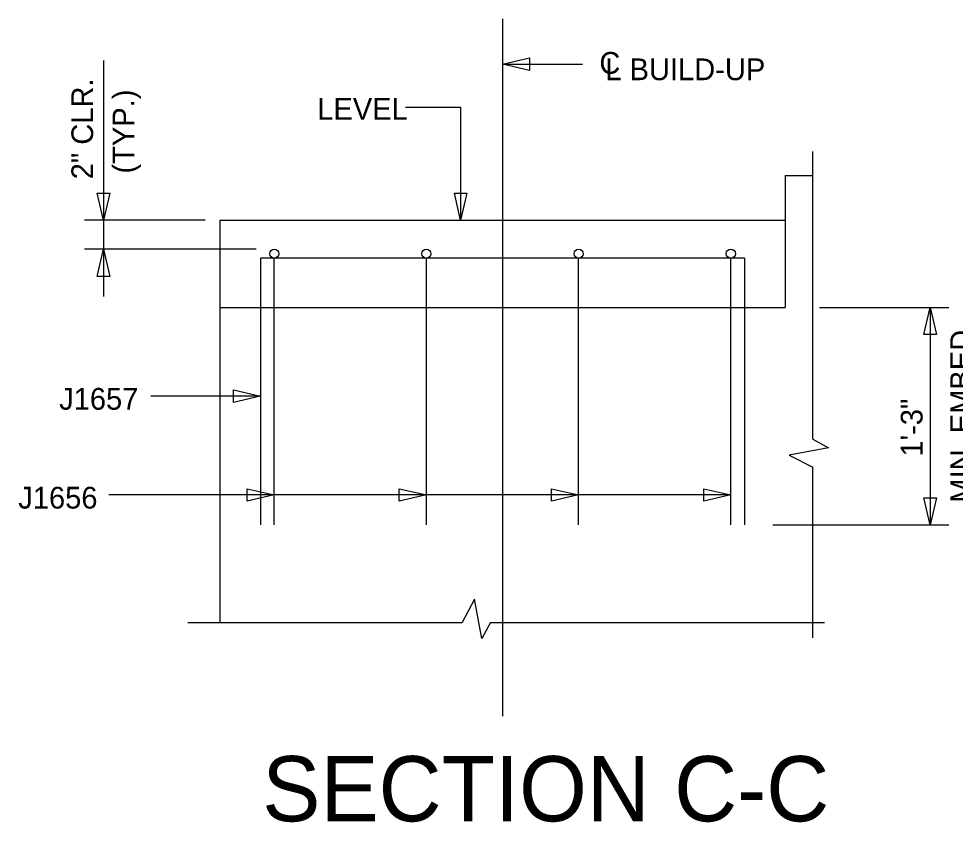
# Model space of a CAD drawing. Extents: x -133.1 to -97, y -1.7 to 20.3.
# Drawn here: x -108.44 to -103.06, y 4.57 to 9.19 of the extents above; entities that cross this region are included whole.
import ezdxf

# ---------------------------------------------------------------- set-up
doc = ezdxf.new("R2010")
doc.units = 0
for name, color, linetype in [('BR_AUTO DIMENSION', 7, 'Continuous'), ('BR_CENTER LINES', 7, 'Continuous'), ('BR_CONCRETE', 7, 'Continuous'), ('BR_REBAR', 7, 'Continuous'), ('BR_TEXT', 7, 'Continuous'), ('Default', 7, 'Continuous')]:
    doc.layers.add(name, color=color, linetype=linetype)

msp = doc.modelspace()

# ---------------------------------------------------------------- linework, layer by layer
at = {"layer": 'BR_AUTO DIMENSION'}
for p, q in [((-107.9547, 8.9515), (-107.9547, 7.5961)), ((-105.6611, 8.9313), (-105.2017, 8.9313)), ((-106.2188, 8.6848), (-105.902, 8.6848)), ((-105.902, 8.6848), (-105.902, 8.0346)), ((-107.3697, 8.0346), (-108.0639, 8.0346)), ((-107.0766, 7.8679), (-108.0639, 7.8679)), ((-103.8393, 7.5336), (-103.0962, 7.5336)), ((-103.2023, 7.5336), (-103.2023, 6.2836)), ((-107.0517, 7.0236), (-107.6836, 7.0236)), ((-104.3486, 6.4554), (-107.9245, 6.4554)), ((-107.7444, 6.4554), (-107.8245, 6.4554)), ((-106.9736, 6.4554), (-107.0537, 6.4554)), ((-106.0986, 6.4554), (-106.1787, 6.4554)), ((-105.2236, 6.4554), (-105.3037, 6.4554)), ((-104.3486, 6.4554), (-104.4287, 6.4554)), ((-104.1075, 6.2836), (-103.0962, 6.2836))]:
    msp.add_line(p, q, dxfattribs=at)
for points in [[(-105.5051, 8.8953), (-105.6611, 8.9313), (-105.5051, 8.9673)], [(-107.9187, 8.1906), (-107.9547, 8.0346), (-107.9907, 8.1906)], [(-105.866, 8.1906), (-105.902, 8.0346), (-105.938, 8.1906)], [(-107.9907, 7.7119), (-107.9547, 7.8679), (-107.9187, 7.7119)], [(-103.2383, 7.3776), (-103.2023, 7.5336), (-103.1663, 7.3776)], [(-107.2077, 7.0596), (-107.0517, 7.0236), (-107.2077, 6.9876)], [(-107.1296, 6.4914), (-106.9736, 6.4554), (-107.1296, 6.4194)], [(-106.2546, 6.4914), (-106.0986, 6.4554), (-106.2546, 6.4194)], [(-105.3796, 6.4914), (-105.2236, 6.4554), (-105.3796, 6.4194)], [(-104.5046, 6.4914), (-104.3486, 6.4554), (-104.5046, 6.4194)], [(-103.1663, 6.4396), (-103.2023, 6.2836), (-103.2383, 6.4396)]]:
    msp.add_lwpolyline(points, close=True, dxfattribs=at)
at = {"layer": 'BR_CENTER LINES'}
msp.add_line((-105.6611, 9.1925), (-105.6611, 5.1843), dxfattribs=at)
at = {"layer": 'BR_CONCRETE'}
for p, q in [((-104.0361, 8.2914), (-104.0361, 7.5336)), ((-104.0361, 8.2914), (-103.878, 8.2914)), ((-107.2861, 8.0346), (-107.2861, 7.5336)), ((-107.2861, 8.0346), (-104.0361, 8.0346)), ((-107.2861, 7.5336), (-104.0361, 7.5336)), ((-107.2861, 7.5336), (-107.2861, 5.7216))]:
    msp.add_line(p, q, dxfattribs=at)
at = {"layer": 'BR_REBAR'}
for p, q in [((-104.2704, 7.8159), (-107.0517, 7.8159)), ((-107.0517, 7.8159), (-107.0517, 6.2836)), ((-106.9736, 6.2836), (-106.9736, 7.8159)), ((-106.0986, 6.2836), (-106.0986, 7.8159)), ((-105.2236, 6.2836), (-105.2236, 7.8159)), ((-104.3486, 6.2836), (-104.3486, 7.8159)), ((-104.2704, 7.8159), (-104.2704, 6.2836))]:
    msp.add_line(p, q, dxfattribs=at)
for centre in [(-106.9736, 7.8419), (-106.0986, 7.8419), (-105.2236, 7.8419), (-104.3486, 7.8419)]:
    msp.add_circle(centre, 0.0261, dxfattribs=at)
at = {"layer": 'Default'}
for p, q in [((-103.878, 6.7758), (-103.878, 8.43)), ((-103.878, 5.6342), (-103.878, 6.6142)), ((-107.47, 5.7216), (-105.8926, 5.7216)), ((-105.731, 5.7216), (-103.8107, 5.7216))]:
    msp.add_line(p, q, dxfattribs=at)
for points in [[(-103.878, 6.7758), (-103.7866, 6.7262), (-104.0128, 6.6837), (-103.878, 6.6142)], [(-105.731, 5.7216), (-105.7806, 5.6302), (-105.8231, 5.8564), (-105.8926, 5.7216)]]:
    msp.add_lwpolyline(points, dxfattribs=at)

# ---------------------------------------------------------------- texts
at = {"layer": 'BR_AUTO DIMENSION'}
for s, p in [('C', (-105.1045, 8.8763)), ('L BUILD-UP', (-105.0702, 8.8393))]:
    msp.add_text(s, height=0.125, dxfattribs=at).set_placement(p)
for s, height, rotation, p in [('2" CLR.', 0.125, 90, (-108.0145, 8.2697)), ('(TYP.)', 0.125, 90, (-107.777, 8.3027)), ('LEVEL', 0.125, 360, (-106.7261, 8.6118)), ('MIN. EMBED.', 0.125002, 90, (-102.9625, 6.4107)), ('J1657', 0.125, 360, (-108.21, 6.9454)), ('1\'-3" ', 0.125, 90, (-103.2464, 6.6759)), ('J1656', 0.125, 360, (-108.445, 6.3772))]:
    msp.add_text(s, height=height, rotation=rotation, dxfattribs=at).set_placement(p)
at = {"layer": 'BR_TEXT'}
msp.add_text('SECTION C-C', height=0.375005, rotation=360, dxfattribs=at).set_placement((-107.0426, 4.5796))

doc.saveas('drawing.dxf')
